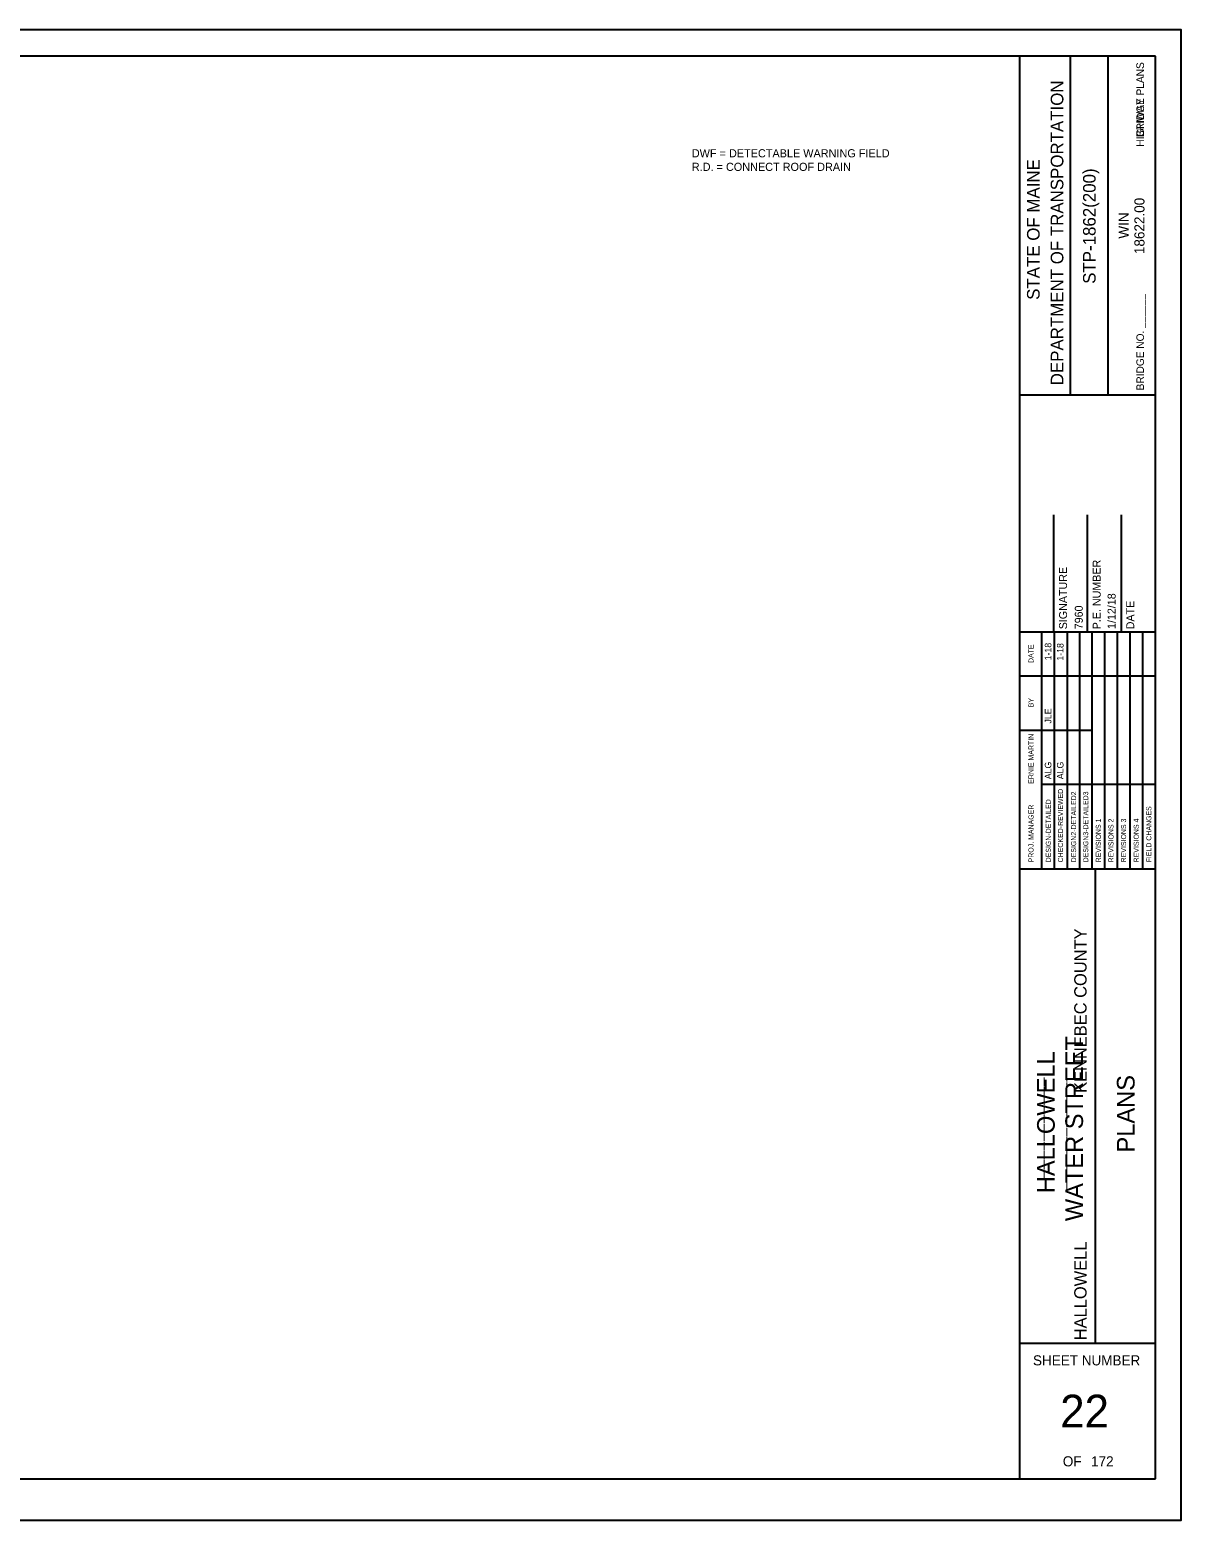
# Model space of a CAD drawing. Extents: x 0 to 850, y 0 to 550.
# Drawn here: x 425 to 850, y 0 to 550 of the extents above; entities that cross this region are included whole.
import ezdxf

# ---------------------------------------------------------------- set-up
doc = ezdxf.new("R2010")
doc.units = 0
for name, color, linetype in [('ANNOTATION', 7, 'Continuous'), ('BORDER', 7, 'Continuous'), ('BRIDGE_TITLE', 7, 'Continuous'), ('Default', 7, 'Continuous'), ('HIGHWAY_TITLE', 7, 'Continuous'), ('PLOT BOUNDARY', 7, 'Continuous')]:
    doc.layers.add(name, color=color, linetype=linetype)

msp = doc.modelspace()

# ---------------------------------------------------------------- linework, layer by layer
at = {"layer": 'BORDER'}
for p, q in [((840.33, 540.24), (40.33, 540.24)), ((790.33, 15.26), (790.33, 540.26)), ((808.97, 415.23), (808.97, 540.23)), ((822.95, 415.23), (822.95, 540.23)), ((840.33, 15.26), (840.33, 540.26)), ((790.34, 415.22), (840.33, 415.22)), ((802.83, 327.76), (802.83, 371)), ((815.33, 327.76), (815.33, 371)), ((827.83, 327.76), (827.83, 371)), ((790.33, 327.76), (840.33, 327.76)), ((790.33, 240.26), (840.33, 240.26)), ((818.29, 65.26), (818.29, 240.26)), ((790.33, 65.26), (840.33, 65.26)), ((40.33, 15.24), (840.33, 15.24))]:
    msp.add_line(p, q, dxfattribs=at)
for points in [[(798.41, 311.51), (798.41, 327.76)], [(803.07, 240.27), (803.07, 327.76)], [(807.73, 327.76), (807.73, 240.27)], [(812.39, 240.27), (812.39, 327.76)], [(817.04, 240.27), (817.04, 327.76)], [(821.7, 240.27), (821.7, 327.76)], [(826.36, 240.27), (826.36, 327.76)], [(831.02, 240.27), (831.02, 327.76)], [(835.68, 240.27), (835.68, 327.76)], [(798.41, 240.27), (798.41, 324.23)], [(790.33, 311.51), (840.33, 311.51)], [(790.33, 291.51), (798.41, 291.51)], [(798.41, 291.51), (817.04, 291.51)], [(798.41, 271.51), (840.33, 271.51)]]:
    msp.add_lwpolyline(points, dxfattribs=at)
at = {"layer": 'Default'}
msp.add_lwpolyline([(40.33, 15.24), (790.33, 15.24), (790.33, 540.26), (40.33, 540.26)], close=True, dxfattribs=at)
at = {"layer": 'PLOT BOUNDARY'}
msp.add_lwpolyline([(-0.13, -0.05), (849.87, -0.05), (849.87, 549.95), (-0.13, 549.95)], close=True, dxfattribs=at)

# ---------------------------------------------------------------- texts
at = {"layer": 'ANNOTATION'}
for s, p in [('DWF = DETECTABLE WARNING FIELD', (669.23, 502.88)), ('R.D. = CONNECT ROOF DRAIN', (669.23, 497.88))]:
    msp.add_text(s, height=3, dxfattribs=at).set_placement(p)
at = {"layer": 'BORDER'}
for s, height, p in [('DEPARTMENT OF TRANSPORTATION', 4.6588, (806.37, 418.77)), ('STATE OF MAINE', 4.6588, (797.61, 450.3)), ('STP-1862(200)', 4.6588, (818.29, 456.21)), ('18622.00', 3.726, (836.31, 467.18)), ('WIN', 3.726, (830.52, 472.89)), ('P.E. NUMBER', 2.9528, (820.14, 328.72)), ('SIGNATURE', 2.953, (807.73, 328.72)), ('1/12/18', 2.953, (825.65, 328.83)), ('7960', 2.953, (813.54, 328.72)), ('DATE', 2.953, (832.54, 328.72)), ('DATE', 1.857, (795.35, 316.29)), ('1-18', 2.423, (801.95, 317.25)), ('1-18', 2.423, (806.42, 317.14)), ('BY', 1.857, (795.35, 299.93)), ('JLE', 2.423, (801.95, 293.93)), ('ERNIE MARTIN', 1.8637, (795.35, 271.72)), ('ALG', 2.423, (801.95, 273.38)), ('ALG', 2.423, (806.42, 273.38)), ('DESIGN-DETAILED', 1.8637, (801.76, 242.7)), ('CHECKED-REVIEWED', 1.8637, (806.24, 242.7)), ('DESIGN2-DETAILED2', 1.8637, (811.08, 242.7)), ('DESIGN3-DETAILED3', 1.8637, (815.55, 242.7)), ('PROJ. MANAGER', 1.8637, (795.35, 242.7)), ('FIELD CHANGES', 1.8637, (838.85, 242.7)), ('REVISIONS 1', 1.8637, (820.21, 242.7)), ('REVISIONS 2', 1.8637, (824.87, 242.7)), ('REVISIONS 3', 1.8637, (829.53, 242.7)), ('REVISIONS 4', 1.8637, (834.19, 242.7)), ('PLANS', 6.521, (832.66, 135.64))]:
    msp.add_text(s, height=height, rotation=90, dxfattribs=at).set_placement(p)
for s, height, p in [('SHEET NUMBER', 3.7264, (795.16, 57.08)), ('22', 12.097, (805.21, 34.16)), ('OF', 3.726, (806.17, 19.81)), ('172', 3.726, (816.61, 19.81))]:
    msp.add_text(s, height=height, dxfattribs=at).set_placement(p)
at = {"layer": 'BRIDGE_TITLE'}
for s, height, p in [('BRIDGE PLANS', 2.795, (836.12, 510.37)), ('BRIDGE NO. ______', 2.795, (836.12, 416.9)), ('KENNEBEC COUNTY', 4.5358, (814.93, 157.65)), ('_____________', 4.5358, (806.55, 121.2)), ('___________', 4.5358, (798.16, 126.17)), ('HALLOWELL', 4.536, (814.93, 66.36))]:
    msp.add_text(s, height=height, rotation=90, dxfattribs=at).set_placement(p)
at = {"layer": 'HIGHWAY_TITLE'}
for s, height, p in [('HIGHWAY PLANS', 2.795, (836.12, 506.82)), ('WATER STREET', 6.5214, (813.63, 110.3)), ('HALLOWELL', 6.521, (803.19, 120.63))]:
    msp.add_text(s, height=height, rotation=90, dxfattribs=at).set_placement(p)

doc.saveas('drawing.dxf')
